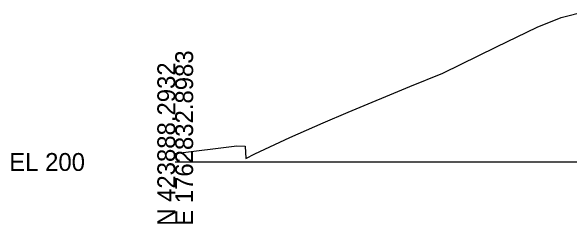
# Model space of a CAD drawing. Extents: x -26 to 3203, y -11010 to 4024.
# Drawn here: x 974.3 to 1061.8, y -9.7 to 23.6 of the extents above; entities that cross this region are included whole.
import ezdxf

# ---------------------------------------------------------------- set-up
doc = ezdxf.new("R2010")
doc.units = 0
for name, color, linetype in [('Default', 7, 'Continuous'), ('Exist Cross Section Cell', 7, 'Continuous'), ('Exist XS Ground Line', 7, 'Continuous')]:
    doc.layers.add(name, color=color, linetype=linetype)

msp = doc.modelspace()

# ---------------------------------------------------------------- linework, layer by layer
at = {"layer": 'Exist Cross Section Cell'}
msp.add_line((1000, 0), (1100, 0), dxfattribs=at)
at = {"layer": 'Exist XS Ground Line'}
msp.add_lwpolyline([(1000, 1.32), (1009.629, 2.534), (1010.943, 2.464), (1011.052, 0.566), (1012.487, 1.266), (1017.974, 3.817), (1023.187, 6.114), (1027.089, 7.823), (1036.745, 11.822), (1041.898, 13.907), (1050.304, 18.05), (1056.706, 21.14), (1060.442, 22.635), (1064.376, 23.633)], dxfattribs=at)
msp.add_lwpolyline([(1000, 1.32), (1009.629, 2.534), (1010.943, 2.464), (1011.052, 0.566), (1012.487, 1.266), (1017.974, 3.817), (1023.187, 6.114), (1027.089, 7.823), (1036.745, 11.822), (1041.898, 13.907), (1050.304, 18.05), (1056.706, 21.14), (1060.442, 22.635), (1064.376, 23.633)], dxfattribs=at)
msp.add_lwpolyline([(1000, 1.32), (1009.629, 2.534), (1010.943, 2.464), (1011.052, 0.566), (1012.487, 1.266), (1017.974, 3.817), (1023.187, 6.114), (1027.089, 7.823), (1036.745, 11.822), (1041.898, 13.907), (1050.304, 18.05), (1056.706, 21.14), (1060.442, 22.635), (1064.376, 23.633)], dxfattribs=at)
msp.add_lwpolyline([(1000, 1.32), (1009.629, 2.534), (1010.943, 2.464), (1011.052, 0.566), (1012.487, 1.266), (1017.974, 3.817), (1023.187, 6.114), (1027.089, 7.823), (1036.745, 11.822), (1041.898, 13.907), (1050.304, 18.05), (1056.706, 21.14), (1060.442, 22.635), (1064.376, 23.633)], dxfattribs=at)
msp.add_lwpolyline([(1000, 1.32), (1009.629, 2.534), (1010.943, 2.464), (1011.052, 0.566), (1012.487, 1.266), (1017.974, 3.817), (1023.187, 6.114), (1027.089, 7.823), (1036.745, 11.822), (1041.898, 13.907), (1050.304, 18.05), (1056.706, 21.14), (1060.442, 22.635), (1064.376, 23.633)], dxfattribs=at)

# ---------------------------------------------------------------- texts
at = {"layer": 'Default'}
msp.add_text('-', height=0.0001, dxfattribs=at).set_placement((1000, 0))
msp.add_text('-', height=0.0001, dxfattribs=at).set_placement((1000, 0))
at = {"layer": 'Exist Cross Section Cell'}
for s, p in [('E 1762832.8983', (1002.8, -10)), ('N 423888.2932', (1000, -10))]:
    msp.add_text(s, height=2.8, rotation=90, dxfattribs=at).set_placement(p)
msp.add_text('EL 200', height=2.8, dxfattribs=at).set_placement((974, -1.4))

doc.saveas('drawing.dxf')
